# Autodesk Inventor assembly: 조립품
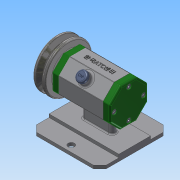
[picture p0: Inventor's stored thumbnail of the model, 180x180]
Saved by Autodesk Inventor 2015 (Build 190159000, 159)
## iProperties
Created: 2018-06
Part Number: 조립품
Document SubType Name: Assembly
Designer: ㅇㅅㅇ
Author: ㅇㅅㅇ
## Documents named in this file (16)
- C:\Users\Administrator\Desktop\480608V1018\조립품.iam
- C:\Users\Administrator\Desktop\480608V1018\본체.ipt
- C:\Users\Administrator\Desktop\480608V1018\앞커버.ipt
- C:\Users\Administrator\Desktop\480608V1018\뒤커버.ipt
- C:\Users\Administrator\Desktop\480608V1018\베어링 15x32x9.ipt
- C:\Users\Administrator\Desktop\480608V1018\볼트 M4x12.ipt
- C:\Users\Administrator\Desktop\480608V1018\오일 실 15 25 7.ipt
- C:\Users\Administrator\Desktop\480608V1018\축.ipt
- C:\Users\Administrator\Desktop\480608V1018\키 3x3x12.ipt
- 키 3x3x12.ipt
- C:\Users\Administrator\Desktop\480608V1018\V벨트풀리.ipt
- C:\Users\Administrator\Desktop\480608V1018\와셔 8x17.ipt
- C:\Users\Administrator\Desktop\480608V1018\스프링와셔 8.ipt
- C:\Users\Administrator\Desktop\480608V1018\너트 M8.ipt
- 너트 M8.ipt
- C:\Users\Administrator\Desktop\480608V1018\고무캡.ipt
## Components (2 placed, 2 different names)
1. V벨트풀리:1
2. 고무캡:1
